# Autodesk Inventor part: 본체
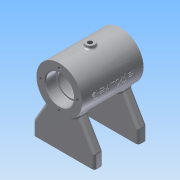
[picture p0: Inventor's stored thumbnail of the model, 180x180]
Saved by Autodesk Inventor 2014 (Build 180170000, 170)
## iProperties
Created: 2018-05
Part Number: 본체
Material: 알루미늄 6061
Document SubType Name: Modeling
Designer: net
Density: 2.71 g/cm^3
Appearance: 알루미늄 - 평지
Mass: 318.857 g
Surface Area: 375.828 cm^2
Volume: 117.66 cm^3
Author: net
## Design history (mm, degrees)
sketch "스케치1"
  geometry: L1 (-35, 0)-(35, 0); L2 (-35, 0)-(-35, 26); L3 (-35, 26)-(35, 26); L4 (35, 26)-(35, 0); 2 further points
  constraints: 8 end point, 2 perpendicular, 1 coincident, 1 horizontal, 1 midpoint, 1 vertical
  dimensions: "d0" = 70 distance of L1.start L1.end; "d1" = 52 diameter of L3 L1
revolve "회전1" sketch "스케치1" stored, may be unused: angle "d2" = 90 deg
hole "구멍1" diameter "d5" = 32; stored, may be unused: countersink angle "d9" = 90 deg, drill point angle "d11" = 0 deg; dims "d3" = 10, "d4" = 10, "d6" = 6, "d7" = 4, "d8" = 2, "d10" = 12
hole "구멍2" diameter "d14" = 28; stored, may be unused: countersink angle "d18" = 90 deg, drill point angle "d20" = 0 deg; dims "d12" = 10, "d13" = 10, "d15" = 6, "d16" = 4, "d17" = 2, "d19" = 2
hole "구멍3" diameter "d23" = 42; stored, may be unused: countersink angle "d27" = 90 deg, drill point angle "d29" = 0 deg; dims "d21" = 10, "d22" = 10, "d24" = 6, "d25" = 4, "d26" = 2, "d28" = 42
hole "구멍4" diameter "d32" = 32; stored, may be unused: countersink angle "d36" = 90 deg, drill point angle "d38" = 0 deg; dims "d30" = 10, "d31" = 10, "d33" = 6, "d34" = 4, "d35" = 2, "d37" = 12
hole "구멍5" diameter "d41" = 28; stored, may be unused: countersink angle "d45" = 90 deg, drill point angle "d47" = 0 deg; dims "d39" = 10, "d40" = 10, "d42" = 6, "d43" = 4, "d44" = 2, "d46" = 2
node "작업 평면1"
sketch "스케치2"
  geometry: C1 r 5 at (0, 0); 1 further point
  constraints: 1 centre point, 1 coincident
  dimensions: "d49" = 10 diameter of C1
extrude "돌출1" join sketch "스케치2" stored distance "d50" = 10; taper "d51" = 0 deg
hole "구멍6" diameter "d54" = 5.188; stored, may be unused: countersink angle "d58" = 90 deg, drill point angle "d60" = 118 deg; dims "d52" = 10, "d53" = 10, "d55" = 6, "d56" = 4, "d57" = 2, "d59" = 12
node "작업 평면2"
sketch "스케치3"
  geometry: L1 (-17.325, -19.386)-(-35, -50); L2 (-35, -50)-(-35, -65); L3 (-35, -65)-(35, -65); L4 (35, -65)-(35, -50); L5 (35, -50)-(17.325, -19.386); A1 r 26 centre (0, 0) between (-17.325, -19.386) and (17.325, -19.386) reference; 2 further points
  constraints: 10 end point, 2 equal length, 2 perpendicular, 2 point on circle, 1 midpoint, 1 vertical, 1 vertical alignment
  dimensions: "d62" = 70 distance between parallel lines of L4 L2; "d63" = 15 distance of L3.end L4.end; "d64" = 65 distance from line of L3 point (0, 0); "d65" = 30 deg angle of L4 L5
extrude "돌출2" join sketch "스케치3" distance "d66" = 10; taper "d67" = 0 deg
sketch "스케치4"
  geometry: L1 (70, 0)-(0, 0) reference; L2 (0, 0)-(0, -10) reference; L3 (70, 0)-(70, -10) reference; 3 further points
  dimensions: "d68" = 40 distance of point (15, -5) point (55, -5); "d69" = 15 distance from line of L3 point (55, -5); "d70" = 15 distance from line of L2 point (15, -5); "d71" = 5 distance from line of L1 point (55, -5)
hole "구멍7" sketch "스케치4" at (55, -5), (15, -5) diameter "d72" = 4.134; stored, may be unused: countersink angle "d76" = 90 deg, drill point angle "d78" = 118 deg; dims "d73" = 8, "d74" = 4, "d75" = 2, "d77" = 10
sketch "스케치5" dims "d79" = 42
  geometry: C1 r 16 at (0, 0) reference; C2 r 26 at (0, 0) reference; 2 further points
  constraints: 2 vertical alignment, 1 coincident, 2 other
hole "구멍8" sketch "스케치5" at (0, 21) diameter "d80" = 3.242; stored, may be unused: countersink angle "d84" = 90 deg, drill point angle "d86" = 118 deg; dims "d81" = 8, "d82" = 4, "d83" = 2, "d85" = 10
sketch "스케치6"
  geometry: L1 (0, 0)-(-9.919, -27.251); L2 (0, 0)-(0, -42.283)
  constraints: 4 end point, 1 vertical
  dimensions: "d90" = 29 distance of L1.start L1.end; "d91" = 20 deg angle of L2 L1
node "작업 평면3"
node "작업 평면4"
node "작업 평면5"
sketch "스케치9"
  geometry: L1 (-35, -26)-(-35, 26) reference; L2 (-35, 26)-(35, 26) reference; 2 further points
  constraints: 1 other
  dimensions: "d107" = 35 distance from line of L1 point (0, 0); "d108" = 26 distance from line of L2 point (0, 0)
feature "엠보싱1" sketch "스케치9" dims "d0" = 70, "d1" = 52, "d109" = 0.5, "d110" = 0
chamfer "모따기1" distance "d111" = 1; stored, may be unused: second distance "d112" = 2, angle "d113" = 45 deg
fillet "모깎기1" dims "d114" = 0.3
fillet "모깎기2" dims "d115" = 2
fillet "모깎기4" dims "d117" = 3
fillet "모깎기5" dims "d118" = 3
fillet "모깎기6" dims "d119" = 3
fillet "모깎기7" dims "d120" = 3
sketch "스케치10"
  geometry: L1 (0, 0)-(9.919, -27.251); L2 (0, 0)-(0, -36.663)
  constraints: 4 end point, 1 vertical
  dimensions: "d124" = 29 distance of L1.start L1.end; "d125" = 20 deg angle of L2 L1; "d126" = 36.6629 distance of L1.start L2.end
node "작업 평면6"
sketch "스케치11"
  geometry: L1 (0, 0)-(29, 0) reference; L2 (29, 0)-(29, 6); L3 (29, 6)-(25, 6); L4 (25, 6)-(25, 0); 1 further point
  constraints: 6 end point, 3 perpendicular, 1 point on line
  dimensions: "d128" = 4 distance of L2.end L3.end; "d129" = 12 diameter of L3 L1
revolve "회전3" sketch "스케치11" stored, may be unused: angle "d130" = 90 deg
hole "구멍10" diameter "d133" = 5.188; stored, may be unused: countersink angle "d137" = 90 deg, drill point angle "d139" = 118 deg; dims "d131" = 10, "d132" = 10, "d134" = 6, "d135" = 4, "d136" = 2, "d138" = 8
fillet "모깎기8" dims "d140" = 2
node "솔리드1"
pattern_circular "원형 패턴1" dims angle "d88" = 360 deg
mirror "대칭1"
mirror "대칭2"
mirror "대칭3"
other parameters: "d48" = 29, "d92" = 90 deg, "d93" = 90 deg, "d106" = 26, "d127" = 90 deg
